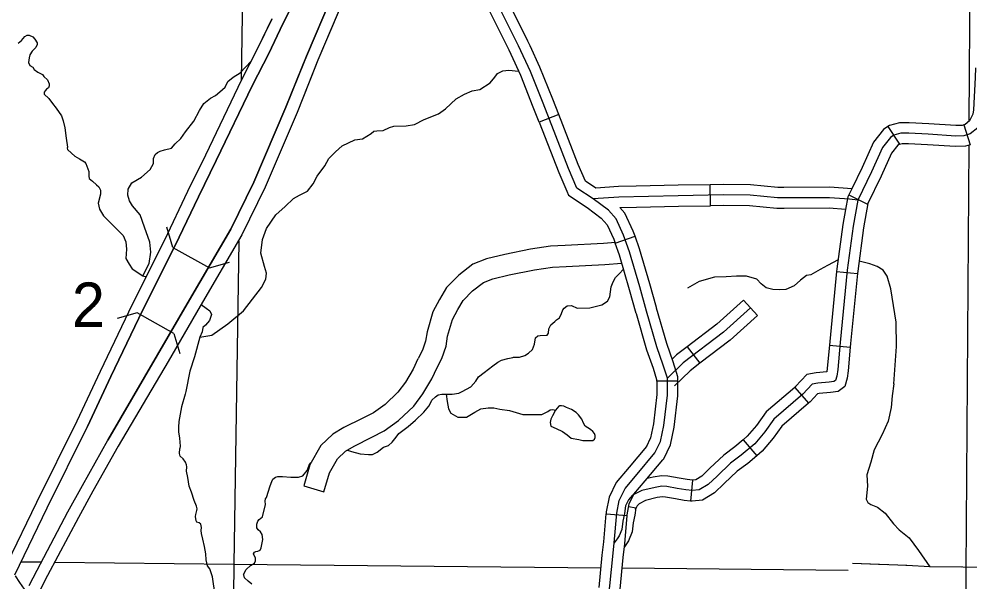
# Model space of a CAD drawing. Extents: x 813775 to 1157140, y 1757555 to 1979907.
# Drawn here: x 972082 to 985663, y 1822306 to 1830349 of the extents above; entities that cross this region are included whole.
import ezdxf

# ---------------------------------------------------------------- set-up
doc = ezdxf.new("R2010")
doc.units = 0
for name, color, linetype in [('Level 19', 7, 'Continuous'), ('Level 31', 7, 'Continuous'), ('Level 32', 7, 'Continuous'), ('Level 35', 7, 'Continuous'), ('Level 37', 7, 'Continuous'), ('Level 39', 7, 'Continuous'), ('Level 4', 7, 'Continuous'), ('Level 43', 7, 'Continuous'), ('Level 46', 7, 'Continuous'), ('Level 5', 7, 'Continuous')]:
    doc.layers.add(name, color=color, linetype=linetype)

msp = doc.modelspace()

# ---------------------------------------------------------------- linework, layer by layer
at = {"layer": 'Level 19'}
for p, q in [((976675, 1831947), (975851, 1830278)), ((975851, 1830278), (976675, 1831947)), ((976933, 1831574), (976188, 1829819)), ((976188, 1829819), (976933, 1831574)), ((977095, 1831516), (976351, 1829762)), ((975692, 1830350), (975489, 1829928)), ((975851, 1830278), (975649, 1829858)), ((975649, 1829858), (975851, 1830278)), ((975489, 1829928), (975260, 1829480)), ((975489, 1829928), (975260, 1829480)), ((975649, 1829858), (975414, 1829405)), ((975414, 1829405), (975649, 1829858)), ((975893, 1829089), (976188, 1829819)), ((976351, 1829762), (976054, 1829015)), ((976188, 1829819), (976152, 1829736)), ((976152, 1829736), (975893, 1829089)), ((976314, 1829677), (976054, 1829015)), ((975260, 1829480), (974745, 1828402)), ((975260, 1829480), (974745, 1828402)), ((975414, 1829405), (974899, 1828327)), ((974899, 1828327), (975414, 1829405)), ((975893, 1829089), (975437, 1828017)), ((975437, 1828017), (975893, 1829089)), ((976054, 1829015), (975598, 1827945)), ((976054, 1829015), (975598, 1827945)), ((974745, 1828402), (974490, 1827883)), ((974745, 1828402), (974490, 1827883)), ((974899, 1828327), (974644, 1827807)), ((974644, 1827807), (974899, 1828327)), ((975437, 1828017), (975107, 1827348)), ((975107, 1827348), (975437, 1828017)), ((975598, 1827945), (975264, 1827267)), ((975598, 1827945), (975264, 1827267)), ((973239, 1825315), (972905, 1824603)), ((973239, 1825315), (972905, 1824603)), ((973393, 1825241), (973058, 1824528)), ((973058, 1824528), (973393, 1825241))]:
    msp.add_line(p, q, dxfattribs=at)
for points in [[(977096, 1831518), (976351, 1829762)], [(975691, 1830347), (975489, 1829928)], [(976349, 1829759), (976314, 1829677)], [(974490, 1827883), (974160, 1827191), (973698, 1826270), (973239, 1825315)], [(974490, 1827883), (974160, 1827191), (973698, 1826270), (973239, 1825315)], [(974644, 1827807), (974314, 1827115), (973851, 1826194), (973393, 1825241)], [(973393, 1825241), (973851, 1826194), (974314, 1827115), (974644, 1827807)], [(975107, 1827348), (974516, 1826338), (974059, 1825550), (973351, 1824331)], [(973351, 1824331), (974059, 1825550), (974516, 1826338), (975107, 1827348)], [(975264, 1827267), (974668, 1826246), (974211, 1825458), (973499, 1824247)], [(975264, 1827267), (974668, 1826246), (974211, 1825458), (973499, 1824247)], [(972905, 1824603), (972332, 1823440), (971907, 1822564)], [(972021, 1822409), (972485, 1823365), (973058, 1824528)], [(972227, 1822257), (972339, 1822476), (972780, 1823310), (972987, 1823686), (973351, 1824331)], [(973499, 1824247), (973135, 1823603), (972930, 1823229), (972490, 1822397), (972289, 1822009)]]:
    msp.add_lwpolyline(points, dxfattribs=at)
at = {"layer": 'Level 31'}
for p, q in [((979790, 1828983), (979511, 1828874)), ((981956, 1827682), (981950, 1827982)), ((980596, 1827147), (980879, 1827246)), ((981491, 1825175), (981191, 1825175)), ((980466, 1823279), (980765, 1823255))]:
    msp.add_line(p, q, dxfattribs=at)
for points in [[(979381, 1829966), (979350, 1830033), (979058, 1830620), (978931, 1830917)], [(979108, 1829841), (979080, 1829904), (978786, 1830494), (978655, 1830799)], [(979790, 1828983), (979705, 1829202), (979521, 1829659), (979381, 1829966)], [(979511, 1828874), (979426, 1829091), (979246, 1829540), (979108, 1829841)], [(985894, 1829791), (985885, 1829507), (985863, 1829031), (985845, 1828942), (985774, 1828796), (985663, 1828707), (985575, 1828680), (985459, 1828676), (985064, 1828703), (984789, 1828716), (984674, 1828716), (984576, 1828689), (984529, 1828658), (984412, 1828512), (984257, 1828165), (984061, 1827761)], [(980170, 1828032), (980068, 1828270), (979790, 1828983)], [(979511, 1828874), (979791, 1828157), (979904, 1827890)], [(980320, 1827932), (980170, 1828032)], [(981950, 1827982), (981493, 1827973), (980894, 1827960)], [(983006, 1827942), (982919, 1827942), (982530, 1827982), (982139, 1827986), (981950, 1827982)], [(979904, 1827890), (979929, 1827831), (980194, 1827656), (980396, 1827505), (980482, 1827409), (980576, 1827204), (980596, 1827147)], [(980894, 1827960), (980641, 1827955), (980320, 1827932)], [(983973, 1827922), (983663, 1827946), (983006, 1827942)], [(984061, 1827761), (983942, 1827774), (983657, 1827796), (982912, 1827792), (982521, 1827832), (982140, 1827836), (981496, 1827823), (980648, 1827805), (980280, 1827779)], [(984061, 1827761), (983995, 1827390), (983910, 1826763), (983808, 1825728), (983773, 1825342), (983760, 1825249), (983742, 1825186), (983720, 1825169), (983653, 1825160), (983489, 1825146)], [(980664, 1827655), (980900, 1827660)], [(980879, 1827246), (980854, 1827317), (980735, 1827575), (980664, 1827655)], [(980900, 1827660), (981499, 1827673), (981956, 1827682)], [(983008, 1827642), (982905, 1827642), (982513, 1827682), (982140, 1827686), (981956, 1827682)], [(983885, 1827628), (983652, 1827646), (983008, 1827642)], [(981186, 1826226), (981090, 1826565), (980942, 1827067), (980879, 1827246)], [(980897, 1826144), (980802, 1826482), (980657, 1826975), (980596, 1827147)], [(981491, 1825175), (981491, 1825239), (981425, 1825450), (981333, 1825711), (981188, 1826218), (981186, 1826226)], [(981191, 1825175), (981191, 1825194), (981141, 1825356), (981047, 1825619), (980899, 1826136), (980897, 1826144)], [(983489, 1825146), (983409, 1825131), (983276, 1824989), (982863, 1824633), (982734, 1824451), (982588, 1824282), (982397, 1824118), (982242, 1824003), (982051, 1823820), (981922, 1823701), (981793, 1823621), (981696, 1823612), (981603, 1823621), (981483, 1823643), (981331, 1823669), (981262, 1823674), (981167, 1823658), (980976, 1823614), (980845, 1823545)], [(981191, 1825175), (981191, 1824985), (981144, 1824565), (981100, 1824364), (981036, 1824232)], [(981275, 1824050), (981290, 1824068), (981386, 1824265), (981440, 1824517), (981491, 1824968), (981491, 1825175)], [(981045, 1824243), (980796, 1823945), (980611, 1823726), (980509, 1823519), (980469, 1823309), (980466, 1823279)], [(980765, 1823255), (980766, 1823268), (980796, 1823423), (980864, 1823561), (981025, 1823752), (981275, 1824050)], [(980845, 1823545), (980785, 1823478), (980743, 1823394), (980727, 1823287), (980703, 1823176), (980690, 1823058), (980654, 1822967), (980623, 1822923), (980583, 1822867)], [(980367, 1822230), (980411, 1822688), (980434, 1822882), (980466, 1823279)], [(980666, 1822202), (980709, 1822656), (980732, 1822852), (980765, 1823255)], [(972395, 1821849), (972191, 1822158), (972093, 1822297), (972030, 1822395)]]:
    msp.add_lwpolyline(points, dxfattribs=at)
at = {"layer": 'Level 32'}
for p, q in [((984488, 1828811), (984655, 1828561)), ((985576, 1828837), (985663, 1828550)), ((983931, 1827836), (984201, 1827705)), ((983758, 1826742), (984056, 1826712)), ((982427, 1826334), (982627, 1826111)), ((983654, 1825690), (983953, 1825663)), ((981624, 1825667), (981806, 1825430)), ((983159, 1825086), (983355, 1824859)), ((982422, 1824338), (982618, 1824110)), ((981699, 1823762), (981671, 1823463)), ((980789, 1823383), (980891, 1823368))]:
    msp.add_line(p, q, dxfattribs=at)
for points in [[(979215, 1829968), (978922, 1830557), (978669, 1831147), (978598, 1831347), (978518, 1831569), (978469, 1831720), (978452, 1831889), (978398, 1832180), (978318, 1832531), (978283, 1832766), (978274, 1832993), (978301, 1833157), (978447, 1833490)], [(980049, 1827932), (979929, 1828214), (979566, 1829147), (979384, 1829600), (979215, 1829968)], [(985740, 1829650), (985735, 1829512), (985714, 1829050), (985702, 1828991), (985654, 1828892), (985592, 1828842), (985576, 1828837)], [(984488, 1828811), (984427, 1828770), (984283, 1828590), (984121, 1828228), (983973, 1827922)], [(985576, 1828837), (985550, 1828829), (985462, 1828826), (985073, 1828852), (984793, 1828866), (984654, 1828866), (984513, 1828827), (984488, 1828811)], [(984655, 1828561), (984632, 1828546), (984541, 1828433), (984393, 1828102), (984201, 1827705)], [(985663, 1828550), (985600, 1828531), (985457, 1828526), (985056, 1828553), (984786, 1828566), (984694, 1828566), (984639, 1828551), (984655, 1828561)], [(981190, 1825665), (981043, 1826177), (980946, 1826523), (980799, 1827021), (980715, 1827261), (980609, 1827492), (980498, 1827616), (980280, 1827779), (980049, 1827932)], [(983973, 1827922), (983931, 1827836)], [(983931, 1827836), (983917, 1827807), (983885, 1827628)], [(984205, 1827714), (984143, 1827367), (984059, 1826746), (984056, 1826712)], [(983885, 1827628), (983847, 1827413), (983761, 1826781), (983758, 1826742)], [(983758, 1826742), (983659, 1825743), (983654, 1825690)], [(984056, 1826712), (983958, 1825714), (983953, 1825663)], [(982527, 1826222), (982141, 1825876), (981568, 1825436), (981341, 1825216)], [(982427, 1826334), (982045, 1825991), (981624, 1825667)], [(982627, 1826111), (982237, 1825760), (981806, 1825430)], [(983654, 1825690), (983624, 1825359), (983616, 1825307), (983468, 1825295), (983333, 1825269), (983172, 1825097), (983159, 1825086)], [(980583, 1822867), (980617, 1823288), (980653, 1823471), (980737, 1823644), (980910, 1823848), (981163, 1824150), (981243, 1824315), (981292, 1824541), (981341, 1824977), (981341, 1825216), (981283, 1825403), (981190, 1825665)], [(981624, 1825667), (981470, 1825550), (981412, 1825494)], [(983953, 1825663), (983922, 1825324), (983907, 1825217), (983873, 1825099), (983781, 1825026), (983669, 1825011), (983509, 1824998), (983485, 1824993), (983380, 1824880), (983355, 1824859)], [(981806, 1825430), (981667, 1825322), (981445, 1825108)], [(983159, 1825086), (982751, 1824735), (982616, 1824544), (982482, 1824389), (982422, 1824338)], [(983355, 1824859), (982975, 1824532), (982853, 1824359), (982694, 1824176), (982618, 1824110)], [(982422, 1824338), (982303, 1824235), (982145, 1824117), (981948, 1823930), (981831, 1823820), (981745, 1823767), (981696, 1823762), (981699, 1823762)], [(982618, 1824110), (982491, 1824001), (982339, 1823888), (982154, 1823711), (982014, 1823581), (981842, 1823474), (981696, 1823461), (981671, 1823463)], [(981699, 1823762), (981623, 1823769), (981509, 1823790), (981349, 1823818), (981255, 1823824), (981138, 1823805), (981054, 1823786)], [(981671, 1823463), (981582, 1823472), (981456, 1823495), (981313, 1823520), (981270, 1823523), (981196, 1823511), (981029, 1823472), (980939, 1823424), (980910, 1823393), (980888, 1823348), (980891, 1823368)], [(980891, 1823368), (980875, 1823260), (980851, 1823151), (980837, 1823022), (980787, 1822896), (980727, 1822810)], [(980062, 1817182), (979961, 1817526), (979867, 1817872), (979805, 1818152), (979734, 1818437), (979699, 1818645), (979685, 1818814), (979708, 1818943), (979810, 1819170), (979941, 1819456), (980063, 1819721), (980151, 1819895), (980276, 1820090), (980435, 1820330), (980498, 1820516), (980502, 1820667), (980475, 1821152), (980453, 1821409), (980462, 1821654), (980502, 1822067), (980560, 1822672), (980583, 1822867)]]:
    msp.add_lwpolyline(points, dxfattribs=at)
at = {"layer": 'Level 35'}
for points in [[(972069, 1830002), (972118, 1830044), (972163, 1830097), (972197, 1830116), (972228, 1830116), (972280, 1830096), (972308, 1830061), (972342, 1830009)], [(972342, 1830009), (972340, 1829983), (972323, 1829940), (972270, 1829891), (972234, 1829837), (972227, 1829792), (972219, 1829728), (972234, 1829683), (972277, 1829659), (972296, 1829628), (972351, 1829591), (972419, 1829556), (972438, 1829526), (972487, 1829479), (972510, 1829424), (972512, 1829395), (972503, 1829365), (972476, 1829345)], [(974157, 1828480), (974258, 1828504), (974313, 1828564), (974392, 1828640), (974457, 1828735), (974579, 1828888), (974658, 1829040), (974720, 1829143), (974816, 1829220), (974889, 1829258), (974949, 1829309), (975028, 1829375), (975066, 1829454), (975139, 1829519), (975239, 1829579), (975397, 1829748)], [(977436, 1828818), (977609, 1828821), (977731, 1828840), (977867, 1828911), (978071, 1828992), (978174, 1829066), (978324, 1829210), (978446, 1829275), (978555, 1829321), (978661, 1829341), (978810, 1829438), (978878, 1829517), (978916, 1829572), (978992, 1829607), (979076, 1829618), (979217, 1829604)], [(972476, 1829345), (972453, 1829325), (972439, 1829304), (972440, 1829275), (972508, 1829215), (972559, 1829142), (972614, 1829075), (972690, 1828966), (972712, 1828894), (972737, 1828794), (972753, 1828645), (972775, 1828520), (972769, 1828502), (972773, 1828486), (972831, 1828433), (972880, 1828389), (972945, 1828350), (973015, 1828308), (973038, 1828285), (973050, 1828248), (973080, 1828172), (973077, 1828128), (973077, 1828105), (973085, 1828072), (973129, 1828032), (973190, 1827981), (973221, 1827951), (973243, 1827904), (973244, 1827847), (973232, 1827789)], [(975751, 1827550), (975882, 1827670), (976001, 1827784), (976088, 1827833), (976200, 1827890), (976281, 1827996), (976341, 1828105), (976447, 1828252), (976507, 1828358), (976602, 1828453), (976697, 1828535), (976879, 1828625), (976985, 1828638), (977113, 1828712), (977148, 1828747), (977192, 1828752), (977284, 1828758), (977371, 1828801), (977436, 1828818)], [(973849, 1826681), (973938, 1826855), (973965, 1827018), (973952, 1827162), (973873, 1827377), (973813, 1827551), (973704, 1827682), (973658, 1827750), (973634, 1827834), (973642, 1827918), (973694, 1828008), (973830, 1828090), (973955, 1828201), (974003, 1828283), (974001, 1828356), (974028, 1828413), (974058, 1828443), (974096, 1828460), (974157, 1828480)], [(973244, 1827847), (973213, 1827717), (973232, 1827633), (973289, 1827537), (973408, 1827418), (973571, 1827257), (973607, 1827168), (973615, 1827061), (973612, 1826996), (973609, 1826928), (973656, 1826849), (973696, 1826779), (973849, 1826681), (973897, 1826666)], [(975607, 1826632), (975615, 1826719), (975588, 1826812), (975537, 1827002), (975558, 1827198), (975618, 1827356), (975751, 1827550)], [(983779, 1826909), (983630, 1826829), (983523, 1826771), (983390, 1826696), (983328, 1826687), (983244, 1826616), (983151, 1826536), (983035, 1826483), (982942, 1826478), (982849, 1826487), (982751, 1826509), (982680, 1826567), (982618, 1826634), (982472, 1826674), (982330, 1826674), (982179, 1826665), (982015, 1826660)], [(979623, 1825832), (979642, 1825863), (979650, 1825925), (979675, 1825980), (979732, 1826026), (979756, 1826053), (979802, 1826078), (979830, 1826140), (979846, 1826192), (979868, 1826219), (979908, 1826252), (979971, 1826255), (980055, 1826219), (980232, 1826222), (980403, 1826268), (980488, 1826317), (980520, 1826380), (980539, 1826521), (980566, 1826592), (980602, 1826655), (980651, 1826709), (980715, 1826776)], [(984575, 1825135), (984615, 1825670), (984606, 1826016), (984531, 1826496), (984478, 1826674), (984424, 1826763), (984336, 1826811), (984234, 1826851), (984079, 1826889)], [(974665, 1825806), (974835, 1825830), (975066, 1825996), (975287, 1826181), (975545, 1826513), (975607, 1826632)], [(982015, 1826660), (981797, 1826598), (981628, 1826505)], [(974683, 1826271), (974754, 1826219), (974809, 1826178), (974830, 1826129), (974803, 1826042), (974746, 1825977), (974708, 1825942), (974695, 1825879), (974665, 1825806)], [(974665, 1825806), (974586, 1825524), (974523, 1825317), (974466, 1825029), (974455, 1824988), (974401, 1824808), (974372, 1824652), (974365, 1824601), (974357, 1824520), (974360, 1824452), (974374, 1824359), (974382, 1824247), (974377, 1824215)], [(978726, 1825301), (978849, 1825394), (978920, 1825445), (978971, 1825475), (979061, 1825500), (979134, 1825511), (979145, 1825516), (979229, 1825519), (979306, 1825541), (979360, 1825573), (979417, 1825628), (979442, 1825704), (979458, 1825794), (979490, 1825821), (979523, 1825826), (979623, 1825832)], [(977743, 1824617), (977865, 1824730), (977933, 1824817), (977952, 1824852), (977979, 1824904), (978028, 1824950), (978069, 1824980), (978120, 1824988), (978180, 1824988), (978267, 1824988), (978362, 1825002), (978411, 1825029), (978533, 1825094), (978604, 1825173), (978642, 1825236), (978726, 1825301)], [(984575, 1825135), (984549, 1824966), (984535, 1824797), (984495, 1824606), (984407, 1824411), (984296, 1824193), (984247, 1824020), (984189, 1823838), (984198, 1823673), (984180, 1823491), (984202, 1823442), (984247, 1823411), (984340, 1823376), (984451, 1823291), (984571, 1823136), (984651, 1823051), (984793, 1822936), (984926, 1822754), (985090, 1822521)], [(978180, 1824988), (978196, 1824887), (978213, 1824781), (978248, 1824719), (978349, 1824659), (978471, 1824662), (978593, 1824732), (978675, 1824779), (978784, 1824792), (978862, 1824792), (978949, 1824776), (979085, 1824757), (979278, 1824697), (979341, 1824697), (979458, 1824697), (979548, 1824700), (979632, 1824741), (979667, 1824768), (979705, 1824770), (979743, 1824762)], [(979743, 1824762), (979699, 1824679), (979676, 1824632), (979665, 1824585), (979676, 1824530), (979755, 1824500), (979845, 1824455), (979908, 1824408), (979965, 1824363), (980076, 1824340), (980134, 1824326), (980197, 1824326), (980248, 1824328), (980277, 1824328), (980300, 1824347), (980312, 1824372), (980309, 1824400), (980300, 1824427), (980278, 1824454), (980241, 1824484), (980167, 1824534), (980141, 1824575), (980118, 1824634), (980073, 1824692), (980040, 1824728), (979971, 1824770), (979899, 1824801), (979861, 1824816), (979830, 1824823), (979800, 1824823), (979789, 1824819), (979743, 1824762)], [(976775, 1824188), (976830, 1824171), (976955, 1824135), (977071, 1824127), (977131, 1824127), (977197, 1824160), (977289, 1824231), (977360, 1824258), (977411, 1824304), (977466, 1824377), (977507, 1824429), (977640, 1824527), (977743, 1824617)], [(974615, 1823391), (974584, 1823470), (974544, 1823590), (974513, 1823674), (974493, 1823798), (974475, 1823889), (974478, 1823952), (974475, 1823982), (974461, 1824018), (974425, 1824065), (974385, 1824105), (974372, 1824144), (974377, 1824215)], [(975560, 1823236), (975601, 1823414), (975598, 1823463), (975603, 1823493), (975617, 1823515), (975666, 1823678), (975693, 1823741), (975707, 1823776), (975745, 1823806), (975777, 1823814), (975843, 1823814), (975965, 1823806), (976074, 1823806), (976136, 1823825), (976199, 1823901), (976234, 1823999), (976243, 1824008)], [(974806, 1822492), (974772, 1822536), (974752, 1822622), (974749, 1822709), (974732, 1822812), (974707, 1822918), (974687, 1822999), (974684, 1823041), (974688, 1823084), (974685, 1823110), (974677, 1823131), (974653, 1823150), (974623, 1823163), (974610, 1823178), (974604, 1823241), (974607, 1823271), (974619, 1823329), (974625, 1823351), (974615, 1823391)], [(975429, 1822710), (975444, 1822733), (975465, 1822744), (975490, 1822749), (975527, 1822760), (975540, 1822795), (975547, 1822844), (975566, 1822911), (975552, 1822984), (975529, 1823023), (975499, 1823051), (975479, 1823081), (975480, 1823133), (975490, 1823175), (975510, 1823201), (975560, 1823236)], [(975407, 1822276), (975353, 1822318), (975301, 1822366), (975290, 1822407), (975289, 1822415), (975324, 1822484), (975389, 1822540), (975446, 1822574), (975461, 1822607), (975460, 1822645), (975429, 1822710)], [(975009, 1821575), (974993, 1821660), (974998, 1821752), (974991, 1821826), (974965, 1821887), (974941, 1821951), (974903, 1822035), (974862, 1822246), (974847, 1822381), (974806, 1822492)]]:
    msp.add_lwpolyline(points, dxfattribs=at)
at = {"layer": 'Level 39'}
for p, q in [((974276, 1827085), (974194, 1827373)), ((974276, 1827085), (974800, 1826792)), ((974800, 1826792), (975088, 1826874)), ((973771, 1826151), (973482, 1826069)), ((974295, 1825858), (973771, 1826151)), ((974295, 1825858), (974377, 1825570))]:
    msp.add_line(p, q, dxfattribs=at)
at = {"layer": 'Level 4'}
for points in [[(985676, 1833175), (985675, 1833040), (985648, 1828887)], [(985646, 1828545), (985605, 1822460), (985613, 1821325)]]:
    msp.add_lwpolyline(points, dxfattribs=at)
at = {"layer": 'Level 43'}
for points in [[(984482, 1822552), (983985, 1822570)], [(985537, 1822516), (985090, 1822521), (984762, 1822543), (984746, 1822543)]]:
    msp.add_lwpolyline(points, dxfattribs=at)
at = {"layer": 'Level 46'}
for points in [[(980599, 1827154), (980430, 1827140), (979883, 1827114), (979671, 1827105), (979388, 1827063), (979019, 1826986), (978757, 1826925), (978562, 1826846), (978361, 1826690), (978186, 1826514), (978085, 1826344), (977992, 1826167), (977910, 1825882), (977888, 1825748), (977843, 1825620), (977781, 1825500)], [(978048, 1825362), (978119, 1825500), (978180, 1825674), (978203, 1825816), (978272, 1826055), (978347, 1826198), (978425, 1826329), (978560, 1826465), (978714, 1826584), (978848, 1826638), (979083, 1826693), (979441, 1826767), (979700, 1826805), (979896, 1826814), (980450, 1826841), (980690, 1826861)], [(977778, 1825493), (977712, 1825347), (977600, 1825161), (977493, 1825017), (977310, 1824842), (977142, 1824722), (976983, 1824643), (976720, 1824511), (976565, 1824416), (976390, 1824257), (976237, 1823981), (976148, 1823681), (976435, 1823595)], [(976435, 1823595), (976515, 1823864), (976628, 1824068), (976746, 1824175), (976866, 1824249), (977118, 1824375), (977297, 1824464), (977502, 1824611), (977718, 1824817), (977850, 1824994), (977978, 1825207), (978051, 1825369)]]:
    msp.add_lwpolyline(points, dxfattribs=at)
at = {"layer": 'Level 5'}
for points in [[(975313, 1833221), (975255, 1829469)], [(975220, 1827175), (975148, 1822561)], [(972112, 1822596), (972401, 1822593)], [(972592, 1822591), (975148, 1822561)], [(975148, 1822561), (975125, 1820328)], [(975148, 1822561), (980394, 1822510)], [(985090, 1822521), (984762, 1822543), (983985, 1822570)], [(980695, 1822507), (983921, 1822476)], [(990236, 1822422), (990221, 1822423), (987780, 1822490), (986497, 1822507), (985090, 1822521)]]:
    msp.add_lwpolyline(points, dxfattribs=at)

# ---------------------------------------------------------------- texts
at = {"layer": 'Level 37'}
msp.add_text('2', height=634, dxfattribs=at).set_placement((972837, 1825951))

doc.saveas('drawing.dxf')
